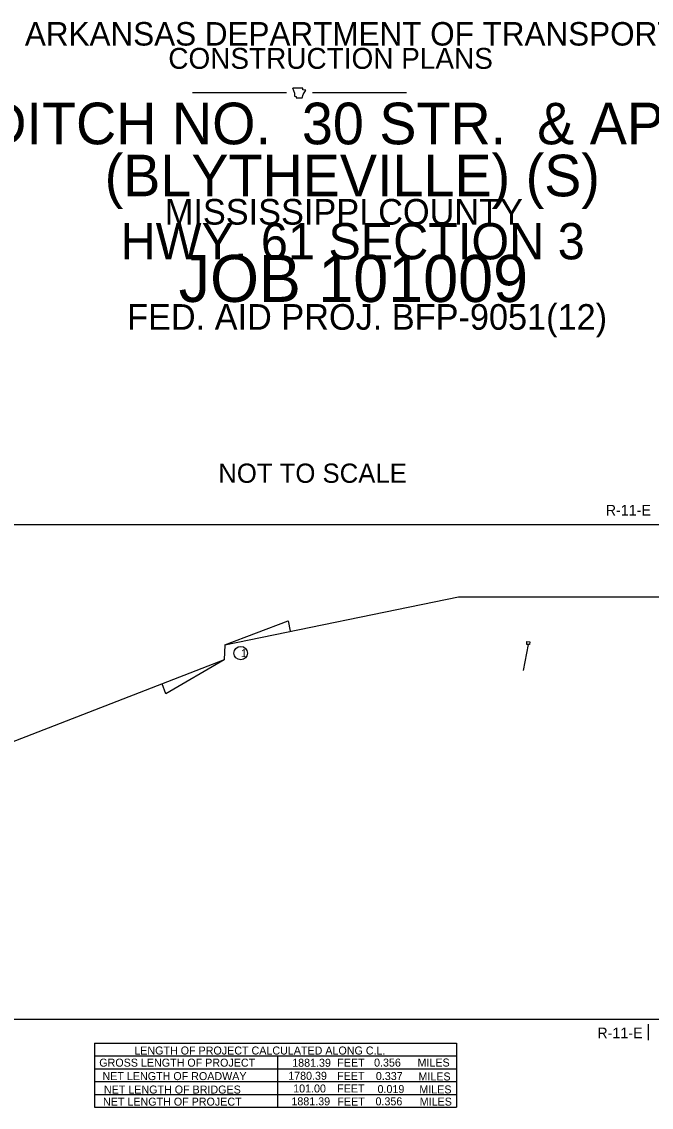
# Model space of a CAD drawing. Extents: x 171 to 3403, y 68 to 2102.
# Drawn here: x 1255 to 2434, y 68 to 2102 of the extents above; entities that cross this region are included whole.
import ezdxf

# ---------------------------------------------------------------- set-up
doc = ezdxf.new("R2010")
doc.units = 0
for name, color, linetype in [('1', 7, 'Continuous'), ('2', 7, 'Continuous'), ('3', 7, 'Continuous'), ('56', 7, 'Continuous'), ('Default', 7, 'Continuous'), ('R_No Plot', 7, 'Continuous')]:
    doc.layers.add(name, color=color, linetype=linetype)

msp = doc.modelspace()

# ---------------------------------------------------------------- linework, layer by layer
at = {"layer": '1'}
for p, q in [((1574.3, 1969.5), (1750.5, 1969.5)), ((1799.4, 1969.5), (1975.5, 1969.5)), ((1635.3, 934.6), (1634, 906.7))]:
    msp.add_line(p, q, dxfattribs=at)
msp.add_lwpolyline([(1761.9, 1978.4), (1765.6, 1968.6), (1765.6, 1962.6), (1768.7, 1961.9), (1768.7, 1959.7), (1779.8, 1959.7), (1782.1, 1965.7), (1786.6, 1973.9), (1781.3, 1974.6), (1781.3, 1977.6), (1762.7, 1977.6)], dxfattribs=at)
at = {"layer": '2'}
msp.add_circle((1664.9, 919.1), 12.6, dxfattribs=at)
at = {"layer": '3'}
for p, q in [((1391.2, 188.4), (1391.2, 68.1)), ((1391.2, 188.4), (2068.7, 188.4)), ((2068.7, 188.4), (2068.7, 68.1)), ((1391.2, 164.3), (2068.7, 164.3)), ((1733.9, 164.3), (1733.9, 68.1)), ((1391.2, 140.3), (2068.7, 140.3)), ((1391.2, 116.2), (2068.7, 116.2)), ((1391.2, 92.1), (2068.7, 92.1)), ((1391.2, 68.1), (2068.7, 68.1))]:
    msp.add_line(p, q, dxfattribs=at)
at = {"layer": '56'}
msp.add_lwpolyline([(2200.4, 935.5), (2200.7, 940.7), (2206, 940.4), (2205.6, 935.2)], close=True, dxfattribs=at)
msp.add_lwpolyline([(2203, 935.3), (2194, 886.3)], dxfattribs=at)
at = {"layer": 'Default'}
msp.add_line((2427.6, 223.8), (2427.6, 194.1), dxfattribs=at)
for points in [[(1635.3, 934.6), (2072.6, 1024.8), (2832.3, 1024.5)], [(1635.3, 934.6), (1753.7, 979.4), (1757.7, 959.9)], [(1634, 906.7), (1178.4, 729.9), (700.6, 730.2)], [(1634, 906.7), (1524.7, 842.9), (1517.5, 861.5)]]:
    msp.add_lwpolyline(points, dxfattribs=at)
at = {"layer": 'R_No Plot'}
msp.add_lwpolyline([(1054.7, 1159.8), (2494.2, 1159.8), (2494.2, 232.8), (1054.7, 232.8)], close=True, dxfattribs=at)

# ---------------------------------------------------------------- texts
at = {"layer": '1'}
for s, p in [('MISSISSIPPI COUNTY', (1522.8, 1722)), ('FED. AID PROJ. BFP-9051(12)', (1452.1, 1525))]:
    msp.add_text(s, height=48, dxfattribs=at).set_placement(p)
at = {"layer": '2'}
for s, height, p in [('ARKANSAS DEPARTMENT OF TRANSPORTATION', 44.03, (1260.7, 2057.5)), ('CONSTRUCTION PLANS', 39.14, (1529.3, 2013.9)), ('DITCH NO.  30 STR.  & APPRS.', 78, (1188.4, 1872.5)), ('(BLYTHEVILLE) (S)', 78, (1410.1, 1775)), ('HWY. 61 SECTION 3', 68, (1440, 1656.9)), ('JOB 101009', 88, (1548.7, 1577.1)), ('NOT TO SCALE', 36, (1622.9, 1238.2)), ('1', 15, (1665.4, 911.5))]:
    msp.add_text(s, height=height, dxfattribs=at).set_placement(p)
at = {"layer": '3'}
for s, p in [('LENGTH OF PROJECT CALCULATED ALONG C.L.', (1465.6, 166.9)), ('GROSS LENGTH OF PROJECT', (1400, 144.2)), ('1881.39', (1761.3, 144)), ('FEET', (1845.7, 144.2)), ('0.356', (1914.6, 144.3)), ('MILES', (1996, 144.4)), ('NET LENGTH OF ROADWAY', (1406.1, 119)), ('1780.39', (1753.8, 119.6)), ('FEET', (1845.4, 119.3)), ('0.337', (1918, 119.1)), ('MILES', (1997.7, 118.3)), ('NET LENGTH OF BRIDGES', (1408.7, 93.8)), ('101.00', (1763.1, 95.8)), ('FEET', (1845.5, 95.8)), ('0.019', (1921.1, 94.7)), ('MILES', (1999.4, 94)), ('NET LENGTH OF PROJECT', (1407, 71.1)), ('1881.39', (1759.8, 71.7)), ('FEET', (1845.9, 71.3)), ('0.356', (1917.3, 71.7)), ('MILES', (2000.1, 71.2))]:
    msp.add_text(s, height=15, dxfattribs=at).set_placement(p)
at = {"layer": 'Default'}
for p in [(2348.4, 1176.9), (2332.7, 197.3)]:
    msp.add_text('R-11-E', height=20, dxfattribs=at).set_placement(p)

doc.saveas('drawing.dxf')
